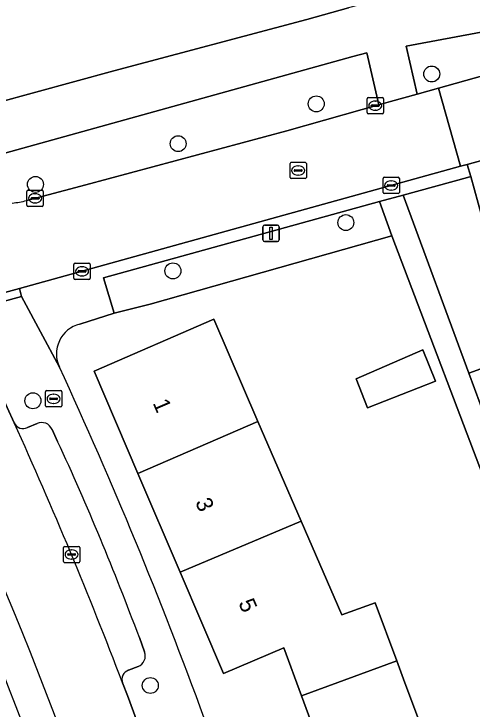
# Model space of a CAD drawing. Extents: x 159053 to 160042, y 380449 to 381423.
# Drawn here: x 159466.61 to 159494.66, y 380957.75 to 381000.34 of the extents above; entities that cross this region are included whole.
import ezdxf

# ---------------------------------------------------------------- set-up
doc = ezdxf.new("R2010")
doc.units = 0
for name, color, linetype in [('IMGEO_Berm_groen', 7, 'Continuous'), ('IMGEO_Boom', 7, 'Continuous'), ('IMGEO_Brandkraan', 7, 'Continuous'), ('IMGEO_Erf', 7, 'Continuous'), ('IMGEO_Groenvoorziening', 7, 'Continuous'), ('IMGEO_Kolk', 7, 'Continuous'), ('IMGEO_Lichtmast', 7, 'Continuous'), ('IMGEO_Pand', 7, 'Continuous'), ('IMGEO_Pand_nummerreeks', 7, 'Continuous'), ('IMGEO_Parkeervlak_open', 7, 'Continuous'), ('IMGEO_Rijbaan_lokaal_open', 7, 'Continuous'), ('IMGEO_Rioolput', 7, 'Continuous'), ('IMGEO_Voetpad_open', 7, 'Continuous')]:
    doc.layers.add(name, color=color, linetype=linetype)

msp = doc.modelspace()

# ---------------------------------------------------------------- linework, layer by layer
at = {"layer": 'IMGEO_Berm_groen'}
msp.add_lwpolyline([(159505.757, 380999.512), (159505.672, 381000), (159505.48, 381001.138), (159500, 381000.115), (159499.383, 381000), (159491.273, 380998.489), (159490.625, 380998.368), (159491.304, 380995.431), (159492.6, 380995.796), (159495.295, 380996.554), (159500, 380997.877)], close=True, dxfattribs=at)
for points in [[(159483.308, 380993.183), (159487.919, 380994.479), (159488.955, 380994.777), (159488.219, 380997.961), (159487.365, 380997.724), (159461.614, 380990.587)], [(159467.388, 380988.905), (159471.019, 380989.869), (159483.308, 380993.183)]]:
    msp.add_lwpolyline(points, dxfattribs=at)
msp.add_arc((159465.89, 380994.787), 6.07, 275.7662, 284.2866, dxfattribs=at)
at = {"layer": 'IMGEO_Boom'}
for centre in [(159492.186, 380996.657), (159485.119, 380994.827), (159476.662, 380992.388), (159467.926, 380989.895), (159486.928, 380987.552), (159476.34, 380984.594), (159467.769, 380976.639), (159474.957, 380959.197)]:
    msp.add_circle(centre, 0.489, dxfattribs=at)
at = {"layer": 'IMGEO_Brandkraan'}
for p, q in [((159468.534, 380976.334), (159468.534, 380977.186)), ((159468.609, 380977.26), (159469.461, 380977.26)), ((159469.535, 380977.186), (159469.535, 380976.334)), ((159468.793, 380976.754), (159468.793, 380976.766)), ((159468.836, 380976.803), (159469.234, 380976.803)), ((159469.022, 380977.04), (159469.047, 380977.04)), ((159469.277, 380976.766), (159469.277, 380976.754)), ((159469.231, 380976.717), (159468.833, 380976.717)), ((159469.045, 380976.48), (159469.02, 380976.48)), ((159469.461, 380976.26), (159468.609, 380976.26))]:
    msp.add_line(p, q, dxfattribs=at)
for points in [[(159468.534, 380976.334), (159468.534, 380977.186)], [(159468.609, 380977.26), (159469.461, 380977.26)], [(159469.535, 380977.186), (159469.535, 380976.334)], [(159469.461, 380976.26), (159468.609, 380976.26)]]:
    msp.add_lwpolyline(points, dxfattribs=at)
for centre, radius, start, end in [((159468.611, 380977.184), 0.0765, 91.552, 178.448), ((159468.611, 380977.184), 0.0765, 91.552, 178.448), ((159469.459, 380977.184), 0.0765, 1.552, 88.448), ((159469.459, 380977.184), 0.0765, 1.552, 88.448), ((159468.833, 380976.763), 0.0403, 85.8775, 175.7526), ((159468.83, 380976.753), 0.0366, 178.938, 274.7102), ((159469.234, 380976.76), 0.043, 264.8664, 352.4533), ((159469.238, 380976.765), 0.0386, 1.7309, 96.639), ((159468.611, 380976.336), 0.0765, 181.552, 268.448), ((159468.611, 380976.336), 0.0765, 181.552, 268.448), ((159469.459, 380976.336), 0.0765, 271.552, 358.448), ((159469.459, 380976.336), 0.0765, 271.552, 358.448)]:
    msp.add_arc(centre, radius, start, end, dxfattribs=at)
for centre, major_axis, ratio, start_param, end_param in [((159469.021, 380976.76), (-0.387, 0.002), 0.722429, 4.712389, 7.853982), ((159469.046, 380976.76), (-0.39, 0.002), 0.717154, 1.570796, 4.712389)]:
    msp.add_ellipse(centre, major_axis=major_axis, ratio=ratio, start_param=start_param, end_param=end_param, dxfattribs=at)
at = {"layer": 'IMGEO_Erf'}
for points in [[(159512.967, 380923.067), (159510.931, 380922.122), (159509.053, 380926.166), (159511.089, 380927.112), (159503.938, 380947.583), (159499.315, 380946.143), (159498.577, 380948.514), (159503.201, 380949.953), (159496.126, 380969.914), (159489.748, 380986.752), (159474.953, 380982.556), (159472.753, 380982.013), (159470.633, 380981.329)], [(159485.276, 380955.689), (159484.213, 380958.564), (159483.125, 380961.505), (159479.447, 380959.93), (159476.787, 380966.141), (159474.2, 380972.183), (159471.515, 380978.455), (159478.837, 380981.63), (159481.548, 380975.375), (159484.193, 380969.272), (159486.682, 380963.528), (159488.734, 380964.268), (159490.05, 380960.707), (159490.467, 380959.578), (159491.332, 380957.235)]]:
    msp.add_lwpolyline(points, dxfattribs=at)
msp.add_lwpolyline([(159488.253, 380976.208), (159487.552, 380977.983), (159491.652, 380979.764), (159492.409, 380977.85)], close=True, dxfattribs=at)
for centre, radius, start, end in [((159471.086, 380979.507), 1.878, 103.9682, 205.5437), ((159218.341, 380862.613), 276.59, 15.17696, 24.81537), ((159219.51, 380862.954), 264.833, 15.18628, 24.98637)]:
    msp.add_arc(centre, radius, start, end, dxfattribs=at)
at = {"layer": 'IMGEO_Groenvoorziening'}
msp.add_lwpolyline([(159465.54, 380994.899), (159472.725, 380996.84), (159484.535, 381000), (159487.099, 381000.703)], dxfattribs=at)
for points in [[(159503.747, 380993.717), (159500, 380992.678), (159496.648, 380991.749), (159494.365, 380991.116), (159494.572, 380990.37), (159495.249, 380987.931), (159500, 380989.358), (159500.456, 380989.495), (159503.219, 380981.99), (159507.276, 380983.365), (159507.194, 380983.605)], [(159474.953, 380982.556), (159489.748, 380986.752), (159488.985, 380988.856), (159472.093, 380984.164), (159472.753, 380982.013)]]:
    msp.add_lwpolyline(points, close=True, dxfattribs=at)
at = {"layer": 'IMGEO_Kolk'}
for p, q in [((159488.23, 380994.29), (159488.23, 380995.142)), ((159488.305, 380995.216), (159489.157, 380995.216)), ((159489.231, 380995.142), (159489.231, 380994.29)), ((159488.489, 380994.71), (159488.489, 380994.722)), ((159488.927, 380994.673), (159488.529, 380994.673)), ((159488.532, 380994.759), (159488.93, 380994.759)), ((159488.718, 380994.996), (159488.743, 380994.996)), ((159488.973, 380994.722), (159488.973, 380994.71)), ((159489.157, 380994.216), (159488.305, 380994.216)), ((159488.741, 380994.436), (159488.716, 380994.436)), ((159489.204, 380989.402), (159489.204, 380990.254)), ((159489.279, 380990.328), (159490.131, 380990.328)), ((159489.692, 380990.108), (159489.717, 380990.108)), ((159490.205, 380990.254), (159490.205, 380989.402)), ((159467.478, 380989.542), (159468.33, 380989.542)), ((159489.463, 380989.822), (159489.463, 380989.834)), ((159489.901, 380989.785), (159489.503, 380989.785)), ((159489.506, 380989.871), (159489.904, 380989.871)), ((159489.715, 380989.548), (159489.69, 380989.548)), ((159489.947, 380989.834), (159489.947, 380989.822)), ((159467.403, 380988.616), (159467.403, 380989.468)), ((159467.891, 380989.322), (159467.916, 380989.322)), ((159468.404, 380989.468), (159468.404, 380988.616)), ((159490.131, 380989.328), (159489.279, 380989.328)), ((159467.662, 380989.036), (159467.662, 380989.048)), ((159468.1, 380988.999), (159467.702, 380988.999)), ((159467.705, 380989.085), (159468.103, 380989.085)), ((159467.914, 380988.762), (159467.889, 380988.762)), ((159468.146, 380989.048), (159468.146, 380989.036)), ((159468.33, 380988.542), (159467.478, 380988.542)), ((159470.275, 380984.142), (159470.275, 380984.994)), ((159470.35, 380985.068), (159471.202, 380985.068)), ((159470.763, 380984.848), (159470.788, 380984.848)), ((159471.276, 380984.994), (159471.276, 380984.142)), ((159470.534, 380984.562), (159470.534, 380984.574)), ((159470.972, 380984.525), (159470.574, 380984.525)), ((159470.577, 380984.611), (159470.975, 380984.611)), ((159471.018, 380984.574), (159471.018, 380984.562)), ((159471.202, 380984.068), (159470.35, 380984.068)), ((159470.786, 380984.288), (159470.761, 380984.288)), ((159469.635, 380966.795), (159469.635, 380967.647)), ((159469.71, 380967.721), (159470.562, 380967.721)), ((159470.123, 380967.501), (159470.148, 380967.501)), ((159470.636, 380967.647), (159470.636, 380966.795)), ((159469.894, 380967.215), (159469.894, 380967.227)), ((159470.332, 380967.178), (159469.934, 380967.178)), ((159469.937, 380967.264), (159470.335, 380967.264)), ((159470.378, 380967.227), (159470.378, 380967.215)), ((159470.562, 380966.721), (159469.71, 380966.721)), ((159470.146, 380966.941), (159470.121, 380966.941))]:
    msp.add_line(p, q, dxfattribs=at)
for points in [[(159488.23, 380994.29), (159488.23, 380995.142)], [(159488.305, 380995.216), (159489.157, 380995.216)], [(159489.231, 380995.142), (159489.231, 380994.29)], [(159489.157, 380994.216), (159488.305, 380994.216)], [(159489.204, 380989.402), (159489.204, 380990.254)], [(159489.279, 380990.328), (159490.131, 380990.328)], [(159490.205, 380990.254), (159490.205, 380989.402)], [(159467.478, 380989.542), (159468.33, 380989.542)], [(159467.403, 380988.616), (159467.403, 380989.468)], [(159468.404, 380989.468), (159468.404, 380988.616)], [(159490.131, 380989.328), (159489.279, 380989.328)], [(159468.33, 380988.542), (159467.478, 380988.542)], [(159470.275, 380984.142), (159470.275, 380984.994)], [(159470.35, 380985.068), (159471.202, 380985.068)], [(159471.276, 380984.994), (159471.276, 380984.142)], [(159471.202, 380984.068), (159470.35, 380984.068)], [(159469.635, 380966.795), (159469.635, 380967.647)], [(159469.71, 380967.721), (159470.562, 380967.721)], [(159470.636, 380967.647), (159470.636, 380966.795)], [(159470.562, 380966.721), (159469.71, 380966.721)]]:
    msp.add_lwpolyline(points, dxfattribs=at)
for centre, radius, start, end in [((159488.307, 380995.14), 0.0765, 91.552, 178.448), ((159488.307, 380995.14), 0.0765, 91.552, 178.448), ((159489.155, 380995.14), 0.0765, 1.552, 88.448), ((159489.155, 380995.14), 0.0765, 1.552, 88.448), ((159488.529, 380994.719), 0.0403, 85.8775, 175.7526), ((159488.526, 380994.709), 0.0366, 178.938, 274.7102), ((159488.93, 380994.716), 0.043, 264.8664, 352.4533), ((159488.934, 380994.721), 0.0386, 1.7309, 96.639), ((159488.307, 380994.292), 0.0765, 181.552, 268.448), ((159488.307, 380994.292), 0.0765, 181.552, 268.448), ((159489.155, 380994.292), 0.0765, 271.552, 358.448), ((159489.155, 380994.292), 0.0765, 271.552, 358.448), ((159489.281, 380990.252), 0.0765, 91.552, 178.448), ((159489.281, 380990.252), 0.0765, 91.552, 178.448), ((159490.129, 380990.252), 0.0765, 1.552, 88.448), ((159490.129, 380990.252), 0.0765, 1.552, 88.448), ((159467.48, 380989.466), 0.0765, 91.552, 178.448), ((159467.48, 380989.466), 0.0765, 91.552, 178.448), ((159468.328, 380989.466), 0.0765, 1.552, 88.448), ((159468.328, 380989.466), 0.0765, 1.552, 88.448), ((159489.503, 380989.831), 0.0403, 85.8775, 175.7526), ((159489.5, 380989.821), 0.0366, 178.938, 274.7102), ((159489.904, 380989.828), 0.043, 264.8664, 352.4533), ((159489.908, 380989.833), 0.0386, 1.7309, 96.639), ((159489.281, 380989.404), 0.0765, 181.552, 268.448), ((159489.281, 380989.404), 0.0765, 181.552, 268.448), ((159490.129, 380989.404), 0.0765, 271.552, 358.448), ((159490.129, 380989.404), 0.0765, 271.552, 358.448), ((159467.702, 380989.045), 0.0403, 85.8775, 175.7526), ((159467.699, 380989.035), 0.0366, 178.938, 274.7102), ((159468.103, 380989.042), 0.043, 264.8664, 352.4533), ((159468.107, 380989.047), 0.0386, 1.7309, 96.639), ((159467.48, 380988.618), 0.0765, 181.552, 268.448), ((159467.48, 380988.618), 0.0765, 181.552, 268.448), ((159468.328, 380988.618), 0.0765, 271.552, 358.448), ((159468.328, 380988.618), 0.0765, 271.552, 358.448), ((159470.352, 380984.992), 0.0765, 91.552, 178.448), ((159470.352, 380984.992), 0.0765, 91.552, 178.448), ((159471.2, 380984.992), 0.0765, 1.552, 88.448), ((159471.2, 380984.992), 0.0765, 1.552, 88.448), ((159470.574, 380984.571), 0.0403, 85.8775, 175.7526), ((159470.571, 380984.561), 0.0366, 178.938, 274.7102), ((159470.975, 380984.568), 0.043, 264.8664, 352.4533), ((159470.979, 380984.573), 0.0386, 1.7309, 96.639), ((159470.352, 380984.144), 0.0765, 181.552, 268.448), ((159470.352, 380984.144), 0.0765, 181.552, 268.448), ((159471.2, 380984.144), 0.0765, 271.552, 358.448), ((159471.2, 380984.144), 0.0765, 271.552, 358.448), ((159469.712, 380967.645), 0.0765, 91.552, 178.448), ((159469.712, 380967.645), 0.0765, 91.552, 178.448), ((159470.56, 380967.645), 0.0765, 1.552, 88.448), ((159470.56, 380967.645), 0.0765, 1.552, 88.448), ((159469.934, 380967.224), 0.0403, 85.8775, 175.7526), ((159469.931, 380967.214), 0.0366, 178.938, 274.7102), ((159470.335, 380967.221), 0.043, 264.8664, 352.4533), ((159470.339, 380967.226), 0.0386, 1.7309, 96.639), ((159469.712, 380966.797), 0.0765, 181.552, 268.448), ((159469.712, 380966.797), 0.0765, 181.552, 268.448), ((159470.56, 380966.797), 0.0765, 271.552, 358.448), ((159470.56, 380966.797), 0.0765, 271.552, 358.448)]:
    msp.add_arc(centre, radius, start, end, dxfattribs=at)
for centre, major_axis, ratio, start_param, end_param in [((159488.717, 380994.716), (-0.387, 0.002), 0.722429, 4.712389, 7.853982), ((159488.742, 380994.716), (-0.39, 0.002), 0.717154, 1.570796, 4.712389), ((159489.691, 380989.828), (-0.387, 0.002), 0.722429, 4.712389, 7.853982), ((159489.716, 380989.828), (-0.39, 0.002), 0.717154, 1.570796, 4.712389), ((159467.89, 380989.042), (-0.387, 0.002), 0.722429, 4.712389, 7.853982), ((159467.915, 380989.042), (-0.39, 0.002), 0.717154, 1.570796, 4.712389), ((159470.762, 380984.568), (-0.387, 0.002), 0.722429, 4.712389, 7.853982), ((159470.787, 380984.568), (-0.39, 0.002), 0.717154, 1.570796, 4.712389), ((159470.122, 380967.221), (-0.387, 0.002), 0.722429, 4.712389, 7.853982), ((159470.147, 380967.221), (-0.39, 0.002), 0.717154, 1.570796, 4.712389)]:
    msp.add_ellipse(centre, major_axis=major_axis, ratio=ratio, start_param=start_param, end_param=end_param, dxfattribs=at)
at = {"layer": 'IMGEO_Lichtmast'}
for p, q in [((159481.953, 380987.396), (159482.743, 380987.396)), ((159482.743, 380987.396), (159481.953, 380987.396)), ((159481.853, 380986.496), (159481.853, 380987.296)), ((159481.853, 380987.296), (159481.853, 380986.496)), ((159482.843, 380987.296), (159482.843, 380986.496)), ((159482.843, 380986.496), (159482.843, 380987.296)), ((159482.743, 380986.396), (159481.953, 380986.396)), ((159481.953, 380986.396), (159482.743, 380986.396))]:
    msp.add_line(p, q, dxfattribs=at)
msp.add_lwpolyline([(159482.273, 380987.271), (159482.423, 380987.271), (159482.423, 380986.521), (159482.273, 380986.521), (159482.273, 380987.271)], dxfattribs=at)
for centre, start, end in [((159481.953, 380987.296), 90, 180), ((159481.953, 380987.296), 90, 180), ((159482.743, 380987.296), 0, 90), ((159482.743, 380987.296), 360, 90), ((159481.953, 380986.496), 180, 270), ((159481.953, 380986.496), 180, 270), ((159482.743, 380986.496), 270, 0), ((159482.743, 380986.496), 270, 0)]:
    msp.add_arc(centre, 0.1, start, end, dxfattribs=at)
at = {"layer": 'IMGEO_Pand'}
for points in [[(159474.2, 380972.183), (159481.548, 380975.375), (159478.837, 380981.63), (159471.515, 380978.455)], [(159487.552, 380977.983), (159488.253, 380976.208), (159492.409, 380977.85), (159491.652, 380979.764)], [(159497.43, 380979.419), (159494.464, 380978.328), (159496.881, 380971.758), (159499.847, 380972.849)], [(159484.193, 380969.272), (159481.548, 380975.375), (159474.2, 380972.183), (159476.787, 380966.141)], [(159484.193, 380969.272), (159476.787, 380966.141), (159479.447, 380959.93), (159483.125, 380961.505), (159484.213, 380958.564), (159490.05, 380960.707), (159488.734, 380964.268), (159486.682, 380963.528)], [(159491.145, 380950.369), (159489.212, 380956.58), (159491.332, 380957.235), (159490.467, 380959.578), (159490.05, 380960.707), (159484.213, 380958.564), (159485.276, 380955.689), (159481.455, 380954.505), (159483.479, 380947.971)]]:
    msp.add_lwpolyline(points, close=True, dxfattribs=at)
at = {"layer": 'IMGEO_Parkeervlak_open'}
for points in [[(159468.021, 380975.251), (159467.434, 380974.996)], [(159469.283, 380974.153), (159468.943, 380974.885)], [(159474.61, 380961.256), (159474.286, 380962.132)], [(159473.625, 380960.134), (159474.208, 380960.363)]]:
    msp.add_lwpolyline(points, dxfattribs=at)
for centre, radius, start, end in [((159220.253, 380863.352), 270.604, 20.77923, 24.43394), ((159467.169, 380975.535), 0.6, 204.4592, 296.2332), ((159468.3, 380974.61), 0.699, 23.1424, 113.5551), ((159312.826, 380901.986), 172.299, 20.43109, 24.76193), ((159473.949, 380961.017), 0.703, 291.6298, 19.8987), ((159473.818, 380959.566), 0.6, 108.7218, 200.6427)]:
    msp.add_arc(centre, radius, start, end, dxfattribs=at)
at = {"layer": 'IMGEO_Rijbaan_lokaal_open'}
msp.add_lwpolyline([(159495.295, 380996.554), (159492.6, 380995.796), (159493.954, 380991.002), (159494.365, 380991.116), (159496.648, 380991.749)], close=True, dxfattribs=at)
for points in [[(159493.954, 380991.002), (159492.6, 380995.796), (159491.304, 380995.431), (159489.661, 380994.969), (159488.955, 380994.777), (159487.919, 380994.479), (159483.308, 380993.183), (159471.019, 380989.869), (159467.388, 380988.905)], [(159449.011, 380983.736), (159447.525, 380983.393), (159431.485, 380978.987), (159432.803, 380974.092), (159448.97, 380978.562), (159455.382, 380980.342), (159466.947, 380983.513), (159493.954, 380991.002)], [(159466.622, 380975.286), (159466.194, 380976.22), (159465.581, 380977.569), (159463.463, 380976.604), (159461.333, 380975.633), (159462.238, 380973.698)], [(159476.1, 380951.506), (159475.977, 380951.861), (159474.827, 380955.127), (159473.55, 380958.575), (159473.256, 380959.354)]]:
    msp.add_lwpolyline(points, dxfattribs=at)
for centre, radius, start, end in [((159465.89, 380994.787), 6.07, 275.7662, 284.2866), ((159220.253, 380863.352), 270.604, 20.77923, 24.43394), ((159233.18, 380867.705), 252.393, 14.9609, 24.8315)]:
    msp.add_arc(centre, radius, start, end, dxfattribs=at)
at = {"layer": 'IMGEO_Rioolput'}
for p, q in [((159483.585, 380991.246), (159484.437, 380991.246)), ((159483.51, 380990.32), (159483.51, 380991.172)), ((159483.998, 380991.026), (159484.023, 380991.026)), ((159484.511, 380991.172), (159484.511, 380990.32)), ((159483.769, 380990.74), (159483.769, 380990.752)), ((159484.207, 380990.703), (159483.809, 380990.703)), ((159483.812, 380990.789), (159484.21, 380990.789)), ((159484.021, 380990.466), (159483.996, 380990.466)), ((159484.253, 380990.752), (159484.253, 380990.74)), ((159484.437, 380990.246), (159483.585, 380990.246))]:
    msp.add_line(p, q, dxfattribs=at)
for points in [[(159483.585, 380991.246), (159484.437, 380991.246)], [(159483.51, 380990.32), (159483.51, 380991.172)], [(159484.511, 380991.172), (159484.511, 380990.32)], [(159484.437, 380990.246), (159483.585, 380990.246)]]:
    msp.add_lwpolyline(points, dxfattribs=at)
for centre, radius, start, end in [((159483.587, 380991.17), 0.0765, 91.552, 178.448), ((159483.587, 380991.17), 0.0765, 91.552, 178.448), ((159484.435, 380991.17), 0.0765, 1.552, 88.448), ((159484.435, 380991.17), 0.0765, 1.552, 88.448), ((159483.809, 380990.749), 0.0403, 85.8775, 175.7526), ((159483.806, 380990.739), 0.0366, 178.938, 274.7102), ((159484.21, 380990.746), 0.043, 264.8664, 352.4533), ((159484.214, 380990.751), 0.0386, 1.7309, 96.639), ((159483.587, 380990.322), 0.0765, 181.552, 268.448), ((159483.587, 380990.322), 0.0765, 181.552, 268.448), ((159484.435, 380990.322), 0.0765, 271.552, 358.448), ((159484.435, 380990.322), 0.0765, 271.552, 358.448)]:
    msp.add_arc(centre, radius, start, end, dxfattribs=at)
for centre, major_axis, ratio, start_param, end_param in [((159483.997, 380990.746), (-0.387, 0.002), 0.722429, 4.712389, 7.853982), ((159484.022, 380990.746), (-0.39, 0.002), 0.717154, 1.570796, 4.712389)]:
    msp.add_ellipse(centre, major_axis=major_axis, ratio=ratio, start_param=start_param, end_param=end_param, dxfattribs=at)
at = {"layer": 'IMGEO_Voetpad_open'}
for points in [[(159491.273, 380998.489), (159499.383, 381000), (159500, 381000.115), (159505.48, 381001.138), (159505.672, 381000), (159505.757, 380999.512), (159507.56, 381000), (159510.493, 381000.794), (159515.537, 381002.185), (159515.381, 381005.067), (159500.763, 381003.012), (159488.332, 381001.222), (159488.348, 381001.046), (159487.099, 381000.703), (159484.535, 381000), (159472.725, 380996.84), (159465.54, 380994.899), (159460.213, 380993.326), (159460.278, 380992.902)], [(159461.614, 380990.587), (159487.365, 380997.724), (159488.219, 380997.961), (159488.955, 380994.777), (159489.661, 380994.969), (159491.304, 380995.431), (159490.625, 380998.368), (159491.273, 380998.489)], [(159472.093, 380984.164), (159488.985, 380988.856), (159490.448, 380989.225), (159494.37, 380990.314), (159494.572, 380990.37), (159494.365, 380991.116), (159493.954, 380991.002), (159466.947, 380983.513), (159467.079, 380983.031), (159469.392, 380978.697)], [(159496.881, 380971.758), (159494.464, 380978.328), (159490.448, 380989.225), (159488.985, 380988.856), (159489.748, 380986.752), (159496.126, 380969.914)], [(159470.633, 380981.329), (159472.753, 380982.013), (159472.093, 380984.164)], [(159469.392, 380978.697), (159467.079, 380983.031), (159455.514, 380979.86), (159455.6, 380979.643), (159456.318, 380977.354)], [(159462.238, 380973.698), (159461.333, 380975.633), (159463.463, 380976.604), (159465.581, 380977.569), (159466.194, 380976.22), (159466.622, 380975.286)], [(159467.434, 380974.996), (159468.021, 380975.251)], [(159468.943, 380974.885), (159469.283, 380974.153)], [(159474.286, 380962.132), (159474.61, 380961.256)], [(159474.208, 380960.363), (159473.625, 380960.134)], [(159473.256, 380959.354), (159473.55, 380958.575), (159474.827, 380955.127), (159475.977, 380951.861), (159476.1, 380951.506)]]:
    msp.add_lwpolyline(points, dxfattribs=at)
for points in [[(159500.456, 380989.495), (159500, 380989.358), (159495.249, 380987.931), (159494.572, 380990.37), (159494.37, 380990.314), (159490.448, 380989.225), (159494.464, 380978.328), (159497.43, 380979.419), (159500.396, 380980.511), (159503.362, 380981.602), (159504.257, 380979.172), (159508.209, 380980.626), (159507.276, 380983.365), (159503.219, 380981.99)], [(159455.382, 380980.342), (159455.514, 380979.86), (159467.079, 380983.031), (159466.947, 380983.513)]]:
    msp.add_lwpolyline(points, close=True, dxfattribs=at)
for centre, radius, start, end in [((159471.086, 380979.507), 1.878, 103.9682, 205.5437), ((159218.341, 380862.613), 276.59, 15.17696, 24.81537), ((159467.169, 380975.535), 0.6, 204.4592, 296.2332), ((159468.3, 380974.61), 0.699, 23.1424, 113.5551), ((159219.51, 380862.954), 264.833, 15.18628, 24.98637), ((159312.826, 380901.986), 172.299, 20.43109, 24.76193), ((159233.18, 380867.705), 252.393, 14.9609, 24.8315), ((159473.949, 380961.017), 0.703, 291.6298, 19.8987), ((159473.818, 380959.566), 0.6, 108.7218, 200.6427)]:
    msp.add_arc(centre, radius, start, end, dxfattribs=at)

# ---------------------------------------------------------------- texts
at = {"layer": 'IMGEO_Pand_nummerreeks'}
for s, p in [('1', (159475.091, 380976.507)), ('3', (159477.69, 380970.437)), ('5', (159480.334, 380964.262))]:
    msp.add_text(s, height=1, rotation=293.1795, dxfattribs=at).set_placement(p)

doc.saveas('drawing.dxf')
